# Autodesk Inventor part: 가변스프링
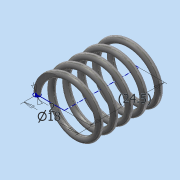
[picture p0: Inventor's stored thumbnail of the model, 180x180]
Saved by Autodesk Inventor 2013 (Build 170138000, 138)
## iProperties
Created: 2018-12
Part Number: 가변스프링
Material: 스테인리스강
Document SubType Name: Modeling
Designer: dgall
Density: 8.08 g/cm^3
Mass: 7.05285 g
Surface Area: 17.7152 cm^2
Volume: 0.872878 cm^3
Author: dgall
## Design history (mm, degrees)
sketch "스케치1"
  geometry: L1 (0, 0)-(0, 24.5); L2 (0, 24.5)-(-9, 24.5); L3 (0, 0)-(-9, 0); C1 r 1 at (-9, 0)
  constraints: 6 end point, 1 centre point, 1 coincident, 1 parallel, 1 perpendicular, 1 vertical, 1 vertical alignment
  dimensions: "d0" = 24.49999 distance of L1.start L1.end (derived); "d1" = 18 diameter of L3.end L1; "d2" = 2 diameter of C1
feature "코일1" pitch "d3" = 10; turns "d5" = 5; dims "d4" = 24.49999 (= d0), "d6" = 0, angle "d7" = 90 deg, angle "d8" = 90 deg, "d9" = 0, "d10" = 0
node "작업 평면1"
feature "분할1"
feature "분할2"
node "솔리드1"
other parameters: "d11" = 0
